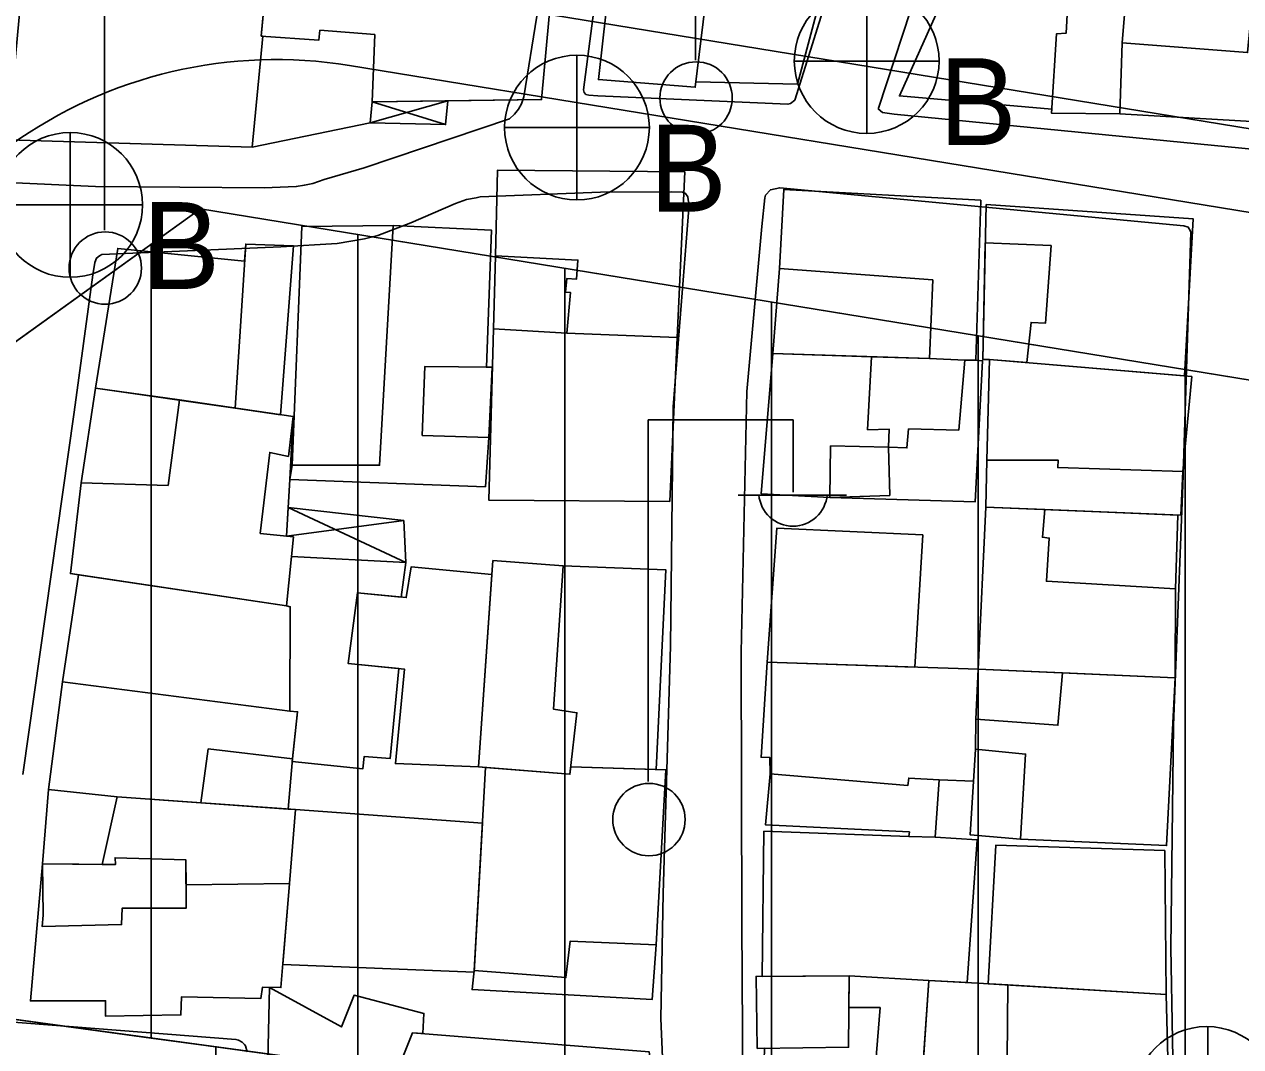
# Model space of a CAD drawing. Extents: x 417997 to 421451, y 4451742 to 4455216.
# Drawn here: x 419230 to 419288.8, y 4453180.8 to 4453230.3 of the extents above; entities that cross this region are included whole.
import ezdxf

# ---------------------------------------------------------------- set-up
doc = ezdxf.new("R2010")
doc.units = 0
for name, color, linetype in [('ADA', 7, 'Continuous'), ('ADAKENARI', 7, 'Continuous'), ('B_Mesken', 7, 'Continuous'), ('B_Sundurma', 7, 'Continuous'), ('B_Teras', 7, 'Continuous'), ('KALDIRIM', 7, 'Continuous'), ('PL_AYA_PARK_DINLENME', 7, 'Continuous'), ('PL_KON_MEV_350', 7, 'Continuous'), ('S_Elektrik_Diregi', 7, 'Continuous'), ('S_Rogar_Kapagi', 7, 'Continuous'), ('S_Rogar_Kapagi_Buski', 7, 'Continuous'), ('TR_ORTAYOGUNKONUT', 7, 'Continuous'), ('Yol_Sose', 7, 'Continuous')]:
    doc.layers.add(name, color=color, linetype=linetype)

msp = doc.modelspace()

# ---------------------------------------------------------------- linework, layer by layer
at = {"layer": 'ADA'}
msp.add_line((419263.499, 4453177.524), (419222.131, 4453183.165), dxfattribs=at)
msp.add_line((419263.499, 4453177.524), (419222.131, 4453183.165), dxfattribs=at)
at = {"layer": 'ADAKENARI'}
for p, q in [((419227.022, 4453213.113), (419238.503, 4453221.37)), ((419227.022, 4453213.113), (419238.503, 4453221.37)), ((419238.503, 4453221.37), (419324.529, 4453207.319)), ((419238.503, 4453221.37), (419324.529, 4453207.319))]:
    msp.add_line(p, q, dxfattribs=at)
at = {"layer": 'B_Mesken'}
for points in [[(419279.68, 4453226.18), (419272.305, 4453226.829), (419276.387, 4453235.935), (419277.388, 4453238.295), (419282.668, 4453237.674), (419283.758, 4453237.553), (419283.438, 4453233.686), (419283.083, 4453229.398), (419282.967, 4453225.966), (419279.668, 4453225.986)], [(419291.145, 4453232.047), (419290.895, 4453228.767), (419291.268, 4453228.773), (419291.019, 4453225.493), (419282.967, 4453225.966), (419283.083, 4453229.398), (419283.811, 4453238.203), (419291.956, 4453237.638), (419291.475, 4453232.031)], [(419268.34, 4453231.018), (419267.372, 4453227.393), (419262.463, 4453227.504), (419262.432, 4453227.249), (419257.75, 4453227.62), (419258.651, 4453235.69), (419269.426, 4453234.823)], [(419230.017, 4453233.617), (419229.187, 4453224.698), (419241.002, 4453224.355), (419241.519, 4453229.714), (419241.446, 4453229.719), (419241.743, 4453232.908), (419240.56, 4453232.958)], [(419246.709, 4453225.529), (419241.002, 4453224.355), (419241.519, 4453229.714), (419241.446, 4453229.719), (419241.848, 4453234.048), (419255.573, 4453232.972), (419255.001, 4453226.646), (419255.001, 4453226.646), (419250.463, 4453226.589), (419250.363, 4453225.438)], [(419252.766, 4453219.093), (419252.872, 4453223.239), (419261.931, 4453223.151), (419261.563, 4453215.138), (419256.222, 4453215.358), (419252.671, 4453215.556)], [(419266.508, 4453218.472), (419266.717, 4453222.302), (419276.24, 4453221.778), (419275.998, 4453214.038), (419275.465, 4453214.047), (419273.763, 4453214.123), (419270.958, 4453214.213), (419266.183, 4453214.367)], [(419276.499, 4453221.567), (419286.506, 4453220.887), (419286.086, 4453213.287), (419276.661, 4453214.078), (419276.342, 4453214.073)], [(419247.82, 4453220.553), (419252.587, 4453220.331), (419252.338, 4453213.703), (419252.612, 4453213.7), (419252.445, 4453210.306), (419252.287, 4453207.923), (419242.833, 4453208.276), (419242.945, 4453208.97), (419243.416, 4453220.514)], [(419233.433, 4453212.689), (419234.509, 4453219.454), (419240.639, 4453218.834), (419240.693, 4453219.659), (419243.003, 4453219.581), (419242.374, 4453211.403), (419240.177, 4453211.726)], [(419261.563, 4453215.138), (419256.222, 4453215.358), (419252.671, 4453215.556), (419252.456, 4453207.273), (419261.203, 4453207.211)], [(419266.183, 4453214.367), (419270.958, 4453214.213), (419273.763, 4453214.123), (419275.465, 4453214.047), (419275.998, 4453214.038), (419276.324, 4453214.02), (419275.964, 4453207.185), (419268.938, 4453207.404), (419265.622, 4453207.587), (419266.183, 4453214.367)], [(419286.455, 4453213.256), (419286.017, 4453208.66), (419285.92, 4453206.549), (419279.346, 4453206.818), (419276.487, 4453206.934), (419276.542, 4453209.213), (419276.661, 4453214.078)], [(419232.738, 4453208.12), (419233.433, 4453212.689), (419237.489, 4453212.121), (419242.987, 4453211.313), (419242.833, 4453208.276), (419242.667, 4453205.53), (419243.001, 4453205.495), (419242.907, 4453204.556), (419242.665, 4453202.157), (419232.616, 4453203.661), (419232.221, 4453203.72)], [(419276.487, 4453206.934), (419276.117, 4453199.092), (419285.639, 4453198.686), (419285.66, 4453202.98), (419285.768, 4453206.555), (419279.346, 4453206.818)], [(419265.916, 4453199.443), (419266.381, 4453205.92), (419273.435, 4453205.589), (419273.058, 4453199.197)], [(419242.907, 4453204.556), (419248.438, 4453204.254), (419248.212, 4453202.585), (419246.096, 4453202.795), (419245.649, 4453199.37), (419248.102, 4453199.124), (419247.681, 4453194.785), (419246.43, 4453194.88), (419246.357, 4453194.278), (419242.939, 4453194.632), (419243.204, 4453197.036), (419242.833, 4453197.071), (419242.845, 4453202.122), (419242.665, 4453202.157)], [(419256.041, 4453204.1), (419261.01, 4453203.905), (419260.537, 4453194.244), (419256.41, 4453194.376), (419256.369, 4453194.02), (419252.289, 4453194.351), (419251.955, 4453194.378), (419252.649, 4453204.351)], [(419231.839, 4453198.492), (419232.616, 4453203.661), (419242.665, 4453202.157), (419242.845, 4453202.122), (419242.833, 4453197.071)], [(419252.602, 4453203.684), (419251.955, 4453194.378), (419247.935, 4453194.535), (419248.378, 4453199.096), (419245.649, 4453199.37), (419246.096, 4453202.795), (419248.459, 4453202.56), (419248.69, 4453204.044)], [(419266.059, 4453194.033), (419265.839, 4453191.566), (419272.788, 4453191.228), (419272.767, 4453191.011), (419274.03, 4453190.97), (419274.224, 4453193.753), (419275.897, 4453193.689), (419275.994, 4453195.226), (419276.002, 4453196.681), (419276.117, 4453199.092), (419265.916, 4453199.443), (419265.621, 4453194.836), (419266.039, 4453194.83)], [(419285.639, 4453198.686), (419285.227, 4453190.566), (419278.164, 4453190.872), (419275.734, 4453191.08), (419275.994, 4453195.226), (419276.002, 4453196.681), (419276.117, 4453199.092), (419280.199, 4453198.918)], [(419242.833, 4453197.071), (419243.204, 4453197.036), (419242.95, 4453194.765), (419242.749, 4453192.332), (419238.519, 4453192.632), (419234.484, 4453192.918), (419231.16, 4453193.273), (419231.839, 4453198.492), (419242.833, 4453197.071)], [(419260.543, 4453185.762), (419260.357, 4453183.126), (419251.642, 4453183.601), (419251.749, 4453184.53), (419252.289, 4453194.351), (419256.369, 4453194.02), (419256.41, 4453194.376), (419261.018, 4453194.228)], [(419231.16, 4453193.273), (419234.484, 4453192.918), (419238.519, 4453192.632), (419242.749, 4453192.332), (419243.107, 4453192.307), (419242.807, 4453188.74), (419237.808, 4453188.664), (419237.801, 4453189.871), (419234.379, 4453189.978), (419234.395, 4453189.649), (419233.749, 4453189.655), (419230.864, 4453189.682)], [(419242.487, 4453184.807), (419242.807, 4453188.74), (419243.107, 4453192.307), (419252.141, 4453191.65), (419251.739, 4453184.448)], [(419276.069, 4453190.837), (419274.03, 4453190.97), (419272.767, 4453191.011), (419265.758, 4453191.257), (419265.663, 4453184.242), (419269.88, 4453184.263), (419273.726, 4453184.043), (419275.591, 4453183.939)], [(419276.601, 4453183.883), (419276.965, 4453190.581), (419285.135, 4453190.323), (419285.208, 4453183.366)], [(419237.808, 4453188.664), (419242.807, 4453188.74), (419242.396, 4453183.694), (419241.5, 4453183.714), (419241.421, 4453183.163), (419237.583, 4453183.244), (419237.563, 4453182.379), (419233.919, 4453182.31), (419233.921, 4453183.062), (419230.286, 4453183.057), (419230.864, 4453189.682), (419234.395, 4453189.649), (419234.379, 4453189.978), (419237.801, 4453189.871)], [(419265.374, 4453184.241), (419269.88, 4453184.263), (419273.726, 4453184.043), (419273.25, 4453177.039), (419273.224, 4453176.649), (419270.895, 4453176.75), (419270.921, 4453177.081), (419265.689, 4453177.287), (419265.776, 4453180.762), (419265.428, 4453180.757)], [(419249.254, 4453181.475), (419249.316, 4453182.449), (419245.935, 4453183.33), (419245.326, 4453181.794), (419241.841, 4453183.706), (419241.626, 4453173.823), (419247.967, 4453173.539), (419248.017, 4453179.656), (419248.763, 4453181.514)], [(419277.55, 4453183.83), (419273.726, 4453184.043), (419273.25, 4453177.039), (419277.491, 4453176.638), (419285.399, 4453175.992), (419285.208, 4453183.366)], [(419247.967, 4453173.539), (419248.017, 4453179.656), (419248.763, 4453181.514), (419260.213, 4453180.588), (419261.208, 4453173.024), (419251.746, 4453173.37)]]:
    msp.add_lwpolyline(points, close=True, dxfattribs=at)
at = {"layer": 'B_Sundurma'}
for p, q in [((419246.709, 4453225.529), (419250.463, 4453226.589)), ((419246.808, 4453226.543), (419250.363, 4453225.438)), ((419248.438, 4453204.254), (419242.751, 4453206.914)), ((419248.336, 4453206.287), (419242.667, 4453205.53))]:
    msp.add_line(p, q, dxfattribs=at)
for points in [[(419246.808, 4453226.543), (419246.709, 4453225.529), (419250.363, 4453225.438), (419250.463, 4453226.589)], [(419248.438, 4453204.254), (419248.336, 4453206.287), (419242.751, 4453206.914), (419242.667, 4453205.53), (419243.001, 4453205.495), (419242.907, 4453204.556)]]:
    msp.add_lwpolyline(points, close=True, dxfattribs=at)
at = {"layer": 'B_Teras'}
for points in [[(419283.083, 4453229.398), (419283.811, 4453238.203), (419291.956, 4453237.638), (419291.475, 4453232.031), (419289.444, 4453232.127), (419289.141, 4453228.923)], [(419257.75, 4453227.62), (419258.651, 4453235.69), (419269.426, 4453234.823), (419268.34, 4453231.018), (419263.008, 4453232.008), (419262.432, 4453227.249)], [(419241.446, 4453229.719), (419241.848, 4453234.048), (419255.573, 4453232.972), (419255.001, 4453226.646), (419246.808, 4453226.543), (419246.932, 4453229.792), (419244.285, 4453230), (419244.226, 4453229.516)], [(419282.967, 4453225.966), (419279.668, 4453225.986), (419279.91, 4453229.834), (419280.366, 4453229.857), (419280.576, 4453233.757), (419283.438, 4453233.686), (419283.083, 4453229.398)], [(419242.945, 4453208.97), (419243.416, 4453220.514), (419247.82, 4453220.553), (419247.171, 4453208.963)], [(419240.693, 4453219.659), (419243.003, 4453219.581), (419242.374, 4453211.403), (419240.177, 4453211.726)], [(419278.474, 4453213.926), (419276.661, 4453214.078), (419276.342, 4453214.073), (419276.461, 4453219.721), (419279.639, 4453219.589), (419279.368, 4453215.832), (419278.674, 4453215.875)], [(419252.671, 4453215.556), (419252.766, 4453219.093), (419256.759, 4453218.882), (419256.694, 4453217.966), (419256.227, 4453218.002), (419256.158, 4453217.337), (419256.407, 4453217.315), (419256.222, 4453215.358)], [(419266.183, 4453214.367), (419266.508, 4453218.472), (419273.92, 4453217.929), (419273.763, 4453214.123)], [(419270.763, 4453210.681), (419270.958, 4453214.213), (419273.763, 4453214.123), (419275.465, 4453214.047), (419275.176, 4453210.66), (419272.748, 4453210.718), (419272.669, 4453209.803), (419271.779, 4453209.841), (419271.818, 4453210.704)], [(419249.224, 4453210.404), (419249.354, 4453213.732), (419252.612, 4453213.7), (419252.445, 4453210.306)], [(419232.221, 4453203.72), (419232.738, 4453208.12), (419236.942, 4453207.987), (419237.489, 4453212.121), (419242.987, 4453211.313), (419242.763, 4453209.386), (419241.853, 4453209.585), (419241.395, 4453205.664), (419243.001, 4453205.495), (419242.665, 4453202.157)], [(419271.779, 4453209.841), (419271.838, 4453207.501), (419268.938, 4453207.404), (419268.982, 4453209.897)], [(419276.487, 4453206.934), (419276.542, 4453209.213), (419279.99, 4453209.208), (419279.968, 4453208.849), (419286.017, 4453208.66), (419285.92, 4453206.549)], [(419276.487, 4453206.934), (419279.346, 4453206.818), (419279.226, 4453205.478), (419279.556, 4453205.437), (419279.42, 4453203.351), (419285.66, 4453202.98), (419285.639, 4453198.686), (419276.117, 4453199.092)], [(419251.955, 4453194.378), (419252.649, 4453204.351), (419256.041, 4453204.1), (419255.578, 4453197.166), (419256.709, 4453196.992), (419256.369, 4453194.02)], [(419276.002, 4453196.681), (419276.117, 4453199.092), (419280.199, 4453198.918), (419279.97, 4453196.387)], [(419242.833, 4453197.071), (419243.204, 4453197.036), (419242.95, 4453194.765), (419238.886, 4453195.244), (419238.519, 4453192.632), (419234.484, 4453192.918), (419231.16, 4453193.273), (419231.839, 4453198.492)], [(419275.734, 4453191.08), (419275.994, 4453195.226), (419278.409, 4453194.991), (419278.164, 4453190.872)], [(419251.749, 4453184.53), (419252.289, 4453194.351), (419256.369, 4453194.02), (419256.41, 4453194.376), (419261.018, 4453194.228), (419260.543, 4453185.762), (419256.38, 4453185.939), (419256.178, 4453184.184)], [(419265.839, 4453191.566), (419266.059, 4453194.033), (419272.717, 4453193.474), (419272.758, 4453193.831), (419274.224, 4453193.753), (419274.03, 4453190.97), (419272.767, 4453191.011), (419272.788, 4453191.228)], [(419234.484, 4453192.918), (419243.107, 4453192.307), (419242.807, 4453188.74), (419237.808, 4453188.664), (419237.801, 4453189.871), (419234.379, 4453189.978), (419234.395, 4453189.649), (419233.749, 4453189.655)], [(419230.898, 4453187.194), (419230.864, 4453189.682), (419234.395, 4453189.649), (419234.379, 4453189.978), (419237.801, 4453189.871), (419237.815, 4453187.541), (419234.718, 4453187.534), (419234.695, 4453186.747), (419230.857, 4453186.65)], [(419265.428, 4453180.757), (419265.374, 4453184.241), (419269.88, 4453184.263), (419269.851, 4453180.812)], [(419270.895, 4453176.75), (419271.372, 4453182.73), (419269.867, 4453182.739), (419269.88, 4453184.263), (419273.726, 4453184.043), (419273.224, 4453176.649)], [(419273.224, 4453176.649), (419273.726, 4453184.043), (419277.55, 4453183.83), (419277.491, 4453176.638), (419273.25, 4453177.039)]]:
    msp.add_lwpolyline(points, close=True, dxfattribs=at)
at = {"layer": 'KALDIRIM'}
for p, q in [((419240.438, 4453233.213), (419361.105, 4453213.504)), ((419240.438, 4453233.213), (419361.105, 4453213.504)), ((419245.714, 4453228.298), (419360.033, 4453209.626)), ((419245.714, 4453228.298), (419360.033, 4453209.626))]:
    msp.add_line(p, q, dxfattribs=at)
msp.add_arc((419242.168, 4453206.586), 22, 80.72359, 170.72359, dxfattribs=at)
msp.add_arc((419242.168, 4453206.586), 22, 80.72359, 170.72359, dxfattribs=at)
at = {"layer": 'PL_AYA_PARK_DINLENME'}
msp.add_lwpolyline([(419226.12, 4453182.621), (419222.131, 4453183.165), (419218.249, 4453159.4), (419226.84, 4453158.31), (419227.381, 4453155.09), (419239.172, 4453154.266), (419239.255, 4453180.83), (419236.12, 4453181.258), (419226.12, 4453182.621)], dxfattribs=at)
msp.add_lwpolyline([(419226.12, 4453182.621), (419222.131, 4453183.165), (419218.249, 4453159.4), (419226.84, 4453158.31), (419227.381, 4453155.09), (419239.172, 4453154.266), (419239.255, 4453180.83), (419236.12, 4453181.258), (419226.12, 4453182.621)], dxfattribs=at)
at = {"layer": 'PL_KON_MEV_350'}
msp.add_lwpolyline([(419305.225, 4453063.565), (419284.03, 4453063.124), (419279.99, 4453063.095), (419275.951, 4453063.174), (419271.915, 4453063.362), (419267.886, 4453063.658), (419263.866, 4453064.063), (419259.859, 4453064.577), (419255.867, 4453065.197), (419251.893, 4453065.925), (419214.319, 4453073.334), (419206.12, 4453085.138), (419211.699, 4453119.301), (419262.248, 4453118.305), (419288.411, 4453117.789), (419284.956, 4453174.598), (419263.499, 4453177.524), (419222.131, 4453183.165), (419227.022, 4453213.113), (419238.503, 4453221.37), (419324.529, 4453207.319)], dxfattribs=at)
at = {"layer": 'S_Elektrik_Diregi'}
for p, q in [((419262.439, 4453228.561), (419262.439, 4453246.061)), ((419233.865, 4453220.336), (419233.865, 4453237.836)), ((419260.161, 4453193.66), (419260.161, 4453211.16)), ((419260.161, 4453211.16), (419267.162, 4453211.16)), ((419267.162, 4453207.66), (419267.162, 4453211.16)), ((419264.502, 4453207.52), (419269.752, 4453207.52))]:
    msp.add_line(p, q, dxfattribs=at)
for centre in [(419262.475, 4453226.726), (419233.901, 4453218.501), (419260.197, 4453191.824)]:
    msp.add_circle(centre, 1.75, dxfattribs=at)
msp.add_arc((419267.162, 4453207.673), 1.658, 184.83843, 355.14641, dxfattribs=at)
at = {"layer": 'S_Rogar_Kapagi'}
msp.add_line((419287.219, 4453174.782), (419287.219, 4453181.782), dxfattribs=at)
msp.add_circle((419287.166, 4453178.31), 3.5, dxfattribs=at)
at = {"layer": 'S_Rogar_Kapagi_Buski'}
for p, q in [((419270.724, 4453232.014), (419270.724, 4453225.014)), ((419256.714, 4453228.794), (419256.714, 4453221.794)), ((419267.224, 4453228.514), (419274.224, 4453228.514)), ((419232.205, 4453225.054), (419232.205, 4453218.054)), ((419253.214, 4453225.294), (419260.214, 4453225.294)), ((419228.705, 4453221.554), (419235.705, 4453221.554))]:
    msp.add_line(p, q, dxfattribs=at)
for centre in [(419270.724, 4453228.514), (419256.714, 4453225.294), (419232.205, 4453221.554)]:
    msp.add_circle(centre, 3.5, dxfattribs=at)
at = {"layer": 'TR_ORTAYOGUNKONUT'}
for p, q in [((419246.12, 4453179.894), (419246.12, 4453220.126)), ((419246.12, 4453179.894), (419246.12, 4453220.126)), ((419236.12, 4453181.258), (419236.12, 4453219.655)), ((419236.12, 4453181.258), (419236.12, 4453219.655)), ((419256.12, 4453178.531), (419256.12, 4453218.492)), ((419256.12, 4453178.531), (419256.12, 4453218.492)), ((419266.12, 4453177.167), (419266.12, 4453216.859)), ((419266.12, 4453177.167), (419266.12, 4453216.859)), ((419276.12, 4453175.803), (419276.12, 4453215.226)), ((419276.12, 4453175.803), (419276.12, 4453215.226)), ((419286.12, 4453155.472), (419286.12, 4453213.592)), ((419286.12, 4453155.472), (419286.12, 4453213.592))]:
    msp.add_line(p, q, dxfattribs=at)
at = {"layer": 'Yol_Sose'}
for points in [[(419269.177, 4453232.812), (419267.25, 4453226.629), (419267.036, 4453226.465), (419266.919, 4453226.427), (419257.719, 4453226.823), (419257.292, 4453226.867), (419257.143, 4453226.9), (419257.059, 4453226.993), (419257.027, 4453227.119), (419258.188, 4453236.058), (419260.034, 4453245.642), (419260.826, 4453250.154), (419261.972, 4453257.743)], [(419290.353, 4453224.152), (419272.053, 4453225.939), (419271.497, 4453226.028), (419271.285, 4453226.199), (419271.292, 4453226.235), (419274.786, 4453236.893)], [(419255.409, 4453234.594), (419254.147, 4453226.789), (419254.024, 4453226.44), (419253.881, 4453226.18), (419253.694, 4453225.95), (419253.452, 4453225.724), (419246.42, 4453223.344), (419244.494, 4453222.786), (419243.938, 4453222.587), (419243.534, 4453222.515), (419243.135, 4453222.442), (419241.581, 4453222.376), (419233.425, 4453222.452), (419228.839, 4453222.653), (419228.757, 4453222.65), (419228.534, 4453222.789), (419228.432, 4453222.961), (419228.416, 4453223.049), (419228.837, 4453230.034)], [(419264.927, 4453212.529), (419265.657, 4453220.518), (419265.795, 4453221.901), (419265.837, 4453222.031), (419266.067, 4453222.29), (419266.518, 4453222.382), (419286.056, 4453220.55), (419286.279, 4453220.471), (419286.389, 4453220.289), (419286.394, 4453220.233), (419286.009, 4453208.001), (419285.567, 4453196.39)], [(419229.921, 4453194.005), (419232.402, 4453211.534), (419233.305, 4453218.168), (419233.397, 4453218.767), (419233.482, 4453218.981), (419233.628, 4453219.09), (419233.734, 4453219.151), (419242.388, 4453219.53), (419245.113, 4453219.695), (419246.446, 4453219.914), (419247.078, 4453220.077), (419248.685, 4453220.69), (419250.835, 4453221.628), (419251.372, 4453221.82), (419251.833, 4453221.898), (419252.033, 4453221.944), (419257.859, 4453222.165), (419261.297, 4453222.184), (419261.819, 4453222.171), (419261.966, 4453222.106), (419262.068, 4453221.938), (419262.098, 4453221.794), (419262.137, 4453221.585), (419261.373, 4453211.784)], [(419285.567, 4453196.39), (419285.435, 4453185.62), (419285.588, 4453176.721), (419285.589, 4453176.492), (419285.564, 4453176.334), (419285.473, 4453176.111), (419285.365, 4453176.017), (419285.071, 4453175.878), (419284.934, 4453175.832), (419272.504, 4453175.932), (419265.053, 4453176.089), (419264.975, 4453176.095), (419264.926, 4453176.112), (419264.763, 4453176.252), (419264.753, 4453176.303), (419264.686, 4453186.812), (419264.652, 4453199.926), (419264.927, 4453212.529)], [(419261.373, 4453211.784), (419261.24, 4453200.207), (419260.886, 4453188.251)], [(419260.886, 4453188.251), (419260.774, 4453182.195), (419260.957, 4453177.668), (419260.955, 4453167.502), (419261.016, 4453154.193)], [(419240.757, 4453180.593), (419240.691, 4453180.873), (419240.637, 4453180.95), (419240.53, 4453181.054), (419240.346, 4453181.158), (419240.224, 4453181.194), (419228.853, 4453182.075)]]:
    msp.add_lwpolyline(points, dxfattribs=at)

# ---------------------------------------------------------------- texts
at = {"layer": 'S_Rogar_Kapagi_Buski'}
for p in [(419274.224, 4453224.45), (419260.214, 4453221.23), (419235.705, 4453217.49)]:
    msp.add_text('B', height=4.2, dxfattribs=at).set_placement(p)

doc.saveas('drawing.dxf')
